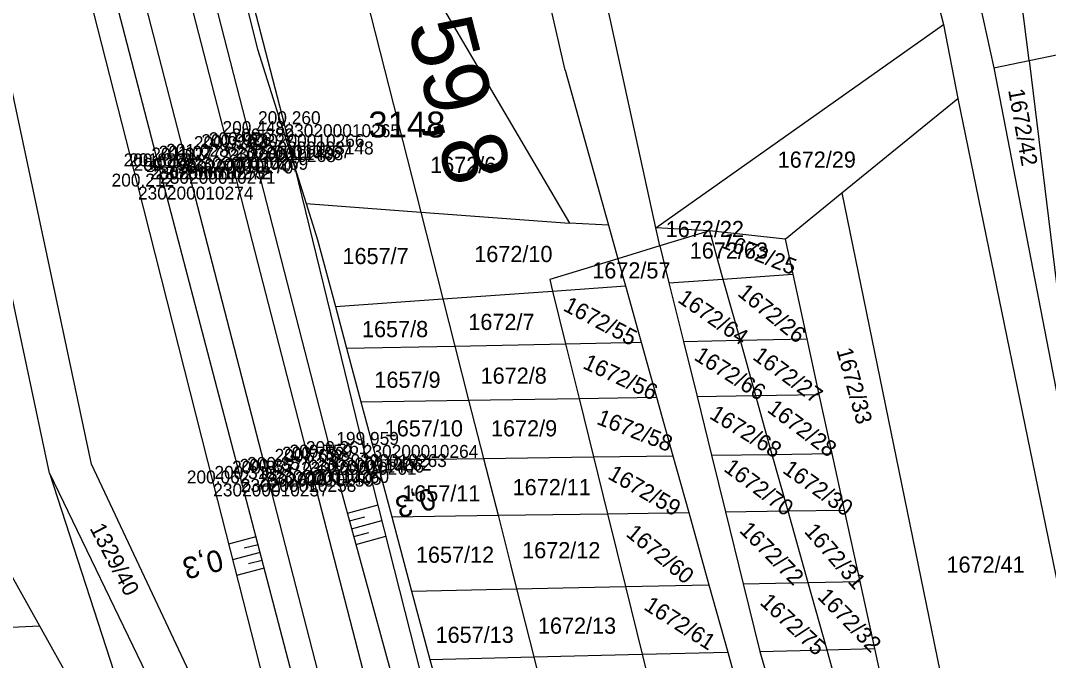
# Model space of a CAD drawing. Extents: x -563148 to -561712, y -1182311 to -1179502.
# Drawn here: x -562432.1 to -562336.8, y -1182001.5 to -1181942.2 of the extents above; entities that cross this region are included whole.
import ezdxf

# ---------------------------------------------------------------- set-up
doc = ezdxf.new("R2010")
doc.units = 0
for name, color, linetype in [('Vrstva 1', 7, 'Continuous'), ('Vrstva 4', 7, 'Continuous'), ('Vrstva 48', 7, 'Continuous'), ('Vrstva 49', 7, 'Continuous'), ('Vrstva 53', 7, 'Continuous'), ('Vrstva 55', 7, 'Continuous'), ('Vrstva 57', 7, 'Continuous'), ('Vrstva 60', 7, 'Continuous'), ('Vrstva 61', 7, 'Continuous'), ('Vrstva 63', 7, 'Continuous'), ('Vrstva 7', 7, 'Continuous')]:
    doc.layers.add(name, color=color, linetype=linetype)

msp = doc.modelspace()

# ---------------------------------------------------------------- linework, layer by layer
at = {"layer": 'Vrstva 1'}
for points in [[(-562431.456, -1181882.158), (-562425.093, -1181906.771), (-562419.091, -1181930.016), (-562412.913, -1181953.965), (-562405.427, -1181982.918), (-562399.924, -1182004.215), (-562394.072, -1182026.888), (-562387.874, -1182050.84), (-562381.86, -1182074.092), (-562375.538, -1182098.521), (-562369.352, -1182122.433), (-562362.844, -1182147.635), (-562356.836, -1182170.919), (-562350.524, -1182195.336)], [(-562435.353, -1181883.455), (-562429.043, -1181907.884), (-562423.025, -1181931.202), (-562416.86, -1181955.033), (-562409.363, -1181984.042), (-562403.855, -1182005.364), (-562398.009, -1182028.011), (-562391.856, -1182051.875), (-562385.852, -1182075.188), (-562379.546, -1182099.541), (-562373.358, -1182123.485), (-562366.843, -1182148.681), (-562360.825, -1182171.976), (-562354.524, -1182196.409)]]:
    msp.add_lwpolyline(points, dxfattribs=at)
at = {"layer": 'Vrstva 4'}
for points in [[(-562356.597, -1182197.058), (-562363.671, -1182172.63), (-562369.111, -1182150.394), (-562376.003, -1182124.384), (-562381.959, -1182100.171), (-562388.242, -1182075.655), (-562394.258, -1182052.529), (-562401.091, -1182025.773), (-562406.12, -1182006.052), (-562411.703, -1181984.696), (-562419.188, -1181956.156), (-562425.491, -1181931.882), (-562431.354, -1181908.293), (-562438.222, -1181883.645), (-562444.124, -1181860.119), (-562450.397, -1181835.425), (-562455.984, -1181813.76), (-562461.844, -1181791.501), (-562470.013, -1181759.746), (-562475.447, -1181735.97), (-562481.267, -1181709.546), (-562485.292, -1181688.623), (-562489.631, -1181662.779), (-562492.854, -1181639.283)], [(-562429.083, -1181881.427), (-562423.039, -1181906.026), (-562416.991, -1181929.289), (-562410.946, -1181952.751), (-562403.313, -1181982.397), (-562397.583, -1182003.414), (-562392.555, -1182023.727), (-562385.634, -1182050.403), (-562379.578, -1182073.569), (-562373.303, -1182097.775), (-562367.317, -1182121.855), (-562360.795, -1182147.202), (-562354.718, -1182170.426), (-562348.388, -1182194.775)]]:
    msp.add_lwpolyline(points, dxfattribs=at)
at = {"layer": 'Vrstva 48'}
for p, q in [((-562401.821, -1181987.868), (-562398.985, -1181987.095)), ((-562401.624, -1181988.592), (-562400.212, -1181988.207)), ((-562401.427, -1181989.315), (-562398.615, -1181988.549)), ((-562410.299, -1181990.068), (-562412.834, -1181990.731)), ((-562401.23, -1181990.039), (-562399.83, -1181989.657)), ((-562401.032, -1181990.763), (-562398.246, -1181990.003)), ((-562410.109, -1181990.794), (-562411.379, -1181991.126)), ((-562409.919, -1181991.519), (-562412.464, -1181992.185)), ((-562409.729, -1181992.245), (-562411.004, -1181992.578)), ((-562409.54, -1181992.971), (-562412.094, -1181993.638))]:
    msp.add_line(p, q, dxfattribs=at)
at = {"layer": 'Vrstva 49'}
for points in [[(-562356.597, -1182197.058), (-562363.671, -1182172.63), (-562369.111, -1182150.394), (-562376.003, -1182124.384), (-562381.959, -1182100.171), (-562388.242, -1182075.655), (-562394.258, -1182052.529), (-562401.091, -1182025.773), (-562406.12, -1182006.052), (-562411.703, -1181984.696), (-562419.188, -1181956.156), (-562425.491, -1181931.882), (-562431.354, -1181908.293), (-562438.222, -1181883.645), (-562444.124, -1181860.119), (-562450.397, -1181835.425), (-562455.984, -1181813.76), (-562461.844, -1181791.501), (-562470.013, -1181759.746), (-562475.447, -1181735.97), (-562481.267, -1181709.546), (-562485.292, -1181688.623), (-562489.631, -1181662.779), (-562492.854, -1181639.283)], [(-562348.388, -1182194.775), (-562346.233, -1182193.909), (-562352.64, -1182170.226), (-562359.021, -1182146.828), (-562365.116, -1182121.8), (-562371.268, -1182096.806), (-562377.938, -1182072.997), (-562383.189, -1182049.641), (-562389.659, -1182023.356), (-562394.989, -1182002.824), (-562400.393, -1181981.55), (-562407.655, -1181951.839), (-562413.753, -1181928.351), (-562419.93, -1181905.004), (-562426.042, -1181880.285)], [(-562429.083, -1181881.427), (-562423.039, -1181906.026), (-562416.991, -1181929.289), (-562410.946, -1181952.751), (-562403.313, -1181982.397), (-562397.583, -1182003.414), (-562392.555, -1182023.727), (-562385.634, -1182050.403), (-562379.578, -1182073.569), (-562373.303, -1182097.775), (-562367.317, -1182121.855), (-562360.795, -1182147.202), (-562354.718, -1182170.426), (-562348.388, -1182194.775)], [(-562439.741, -1181884.96), (-562433.646, -1181909.277), (-562427.61, -1181932.656), (-562421.237, -1181957.617), (-562414.263, -1181985.119), (-562408.778, -1182006.666), (-562403.486, -1182026.149), (-562396.951, -1182053.474), (-562390.332, -1182076.348), (-562384.199, -1182100.797), (-562378.1, -1182124.825), (-562372.04, -1182148.774), (-562365.699, -1182172.919), (-562358.847, -1182197.091), (-562356.597, -1182197.058)]]:
    msp.add_lwpolyline(points, dxfattribs=at)
at = {"layer": 'Vrstva 53'}
for p, q in [((-562420.91, -1181902.74), (-562410.15, -1181944.88)), ((-562410.15, -1181944.88), (-562405.65, -1181959.2)), ((-562425.54, -1181983.33), (-562432.92, -1181948.58)), ((-562405.65, -1181959.2), (-562404.6, -1181962.54)), ((-562404.6, -1181962.54), (-562402.94, -1181968.72)), ((-562402.94, -1181968.72), (-562401.9, -1181972.6)), ((-562401.9, -1181972.6), (-562400.57, -1181977.57)), ((-562400.57, -1181977.57), (-562399.13, -1181982.94)), ((-562399.13, -1181982.94), (-562397.71, -1181988.21)), ((-562403.38, -1182030.44), (-562425.54, -1181983.33)), ((-562397.71, -1181988.21), (-562395.87, -1181995.1)), ((-562395.87, -1181995.1), (-562394.17, -1182001.42)), ((-562394.17, -1182001.42), (-562391.09, -1182012.89))]:
    msp.add_line(p, q, dxfattribs=at)
at = {"layer": 'Vrstva 55'}
for p, q in [((-562372.35, -1181842.15), (-562346.55, -1181942.6)), ((-562338.63, -1181945.94), (-562346.12, -1181884.73)), ((-562373.23, -1181961.44), (-562383.8, -1181913.17)), ((-562381.62, -1181946.84), (-562388.61, -1181916.83)), ((-562405.15, -1181920.27), (-562395.02, -1181959.99)), ((-562405.15, -1181920.27), (-562381.24, -1181961.01)), ((-562343.26, -1181940.43), (-562341.89, -1181946.62)), ((-562373.23, -1181961.44), (-562346.55, -1181942.6)), ((-562346.55, -1181942.6), (-562345.24, -1181949.46)), ((-562338.63, -1181945.94), (-562334.86, -1181945.16)), ((-562341.89, -1181946.62), (-562338.63, -1181945.94)), ((-562341.89, -1181946.62), (-562332.75, -1181993.96)), ((-562338.63, -1181945.94), (-562332.75, -1181993.96)), ((-562381.62, -1181946.84), (-562377.62, -1181961.2)), ((-562355.97, -1181958.2), (-562345.24, -1181949.46)), ((-562345.24, -1181949.46), (-562335.42, -1181997.15)), ((-562361.25, -1181962.5), (-562355.97, -1181958.2)), ((-562355.97, -1181958.2), (-562338.86, -1182041.71)), ((-562405.65, -1181959.2), (-562395.02, -1181959.99)), ((-562395.02, -1181959.99), (-562392.97, -1181968.02)), ((-562395.02, -1181959.99), (-562381.24, -1181961.01)), ((-562377.62, -1181961.2), (-562381.24, -1181961.01)), ((-562377.62, -1181961.2), (-562376.75, -1181964.31)), ((-562372.86, -1181963.12), (-562373.23, -1181961.44)), ((-562368.26, -1181961.71), (-562373.23, -1181961.44)), ((-562368.26, -1181961.71), (-562372.86, -1181963.12)), ((-562361.25, -1181962.5), (-562368.26, -1181961.71)), ((-562368.26, -1181961.71), (-562367.01, -1181966.18)), ((-562361.25, -1181962.5), (-562360.54, -1181965.73)), ((-562372.86, -1181963.12), (-562376.75, -1181964.31)), ((-562372.86, -1181963.12), (-562372.02, -1181966.54)), ((-562429.45, -1181984.16), (-562433.59, -1181964.66)), ((-562376.75, -1181964.31), (-562383.06, -1181966.24)), ((-562376.75, -1181964.31), (-562376.05, -1181966.82)), ((-562367.01, -1181966.18), (-562360.54, -1181965.73)), ((-562360.54, -1181965.73), (-562359.23, -1181971.72)), ((-562383.06, -1181966.24), (-562382.8, -1181967.3)), ((-562372.02, -1181966.54), (-562367.01, -1181966.18)), ((-562372.02, -1181966.54), (-562370.67, -1181971.96)), ((-562367.01, -1181966.18), (-562365.42, -1181971.85)), ((-562392.97, -1181968.02), (-562382.8, -1181967.3)), ((-562382.8, -1181967.3), (-562376.05, -1181966.82)), ((-562382.8, -1181967.3), (-562381.59, -1181972.18)), ((-562376.05, -1181966.82), (-562374.59, -1181972.04)), ((-562402.94, -1181968.72), (-562392.97, -1181968.02)), ((-562392.97, -1181968.02), (-562391.86, -1181972.39)), ((-562401.9, -1181972.6), (-562391.86, -1181972.39)), ((-562391.86, -1181972.39), (-562381.59, -1181972.18)), ((-562391.86, -1181972.39), (-562390.58, -1181977.41)), ((-562381.59, -1181972.18), (-562374.59, -1181972.04)), ((-562381.59, -1181972.18), (-562380.34, -1181977.24)), ((-562374.59, -1181972.04), (-562373.16, -1181977.12)), ((-562370.67, -1181971.96), (-562365.42, -1181971.85)), ((-562370.67, -1181971.96), (-562369.41, -1181977.06)), ((-562365.42, -1181971.85), (-562359.23, -1181971.72)), ((-562365.42, -1181971.85), (-562363.98, -1181976.97)), ((-562359.23, -1181971.72), (-562358.11, -1181976.87)), ((-562380.34, -1181977.24), (-562373.16, -1181977.12)), ((-562373.16, -1181977.12), (-562371.64, -1181982.56)), ((-562369.41, -1181977.06), (-562363.98, -1181976.97)), ((-562369.41, -1181977.06), (-562368.06, -1181982.51)), ((-562363.98, -1181976.97), (-562358.11, -1181976.87)), ((-562363.98, -1181976.97), (-562362.46, -1181982.43)), ((-562358.11, -1181976.87), (-562356.91, -1181982.35)), ((-562400.57, -1181977.57), (-562390.58, -1181977.41)), ((-562390.58, -1181977.41), (-562380.34, -1181977.24)), ((-562390.58, -1181977.41), (-562389.2, -1181982.8)), ((-562380.34, -1181977.24), (-562379, -1181982.66)), ((-562399.13, -1181982.94), (-562389.2, -1181982.8)), ((-562389.2, -1181982.8), (-562379, -1181982.66)), ((-562389.2, -1181982.8), (-562387.86, -1181988.07)), ((-562379, -1181982.66), (-562371.64, -1181982.56)), ((-562379, -1181982.66), (-562377.7, -1181987.92)), ((-562371.64, -1181982.56), (-562370.18, -1181987.8)), ((-562368.06, -1181982.51), (-562362.46, -1181982.43)), ((-562368.06, -1181982.51), (-562366.77, -1181987.75)), ((-562362.46, -1181982.43), (-562356.91, -1181982.35)), ((-562362.46, -1181982.43), (-562360.99, -1181987.66)), ((-562356.91, -1181982.35), (-562355.76, -1181987.59)), ((-562429.45, -1181984.16), (-562399.59, -1182045.91)), ((-562429.45, -1181984.16), (-562417.31, -1182021.52)), ((-562366.77, -1181987.75), (-562360.99, -1181987.66)), ((-562360.99, -1181987.66), (-562355.76, -1181987.59)), ((-562360.99, -1181987.66), (-562359.13, -1181994.3)), ((-562355.76, -1181987.59), (-562354.32, -1181994.2)), ((-562397.71, -1181988.21), (-562387.86, -1181988.07)), ((-562387.86, -1181988.07), (-562377.7, -1181987.92)), ((-562387.86, -1181988.07), (-562386.7, -1181992.62)), ((-562377.7, -1181987.92), (-562370.18, -1181987.8)), ((-562377.7, -1181987.92), (-562376.03, -1181994.67)), ((-562370.18, -1181987.8), (-562368.3, -1181994.5)), ((-562366.77, -1181987.75), (-562365.12, -1181994.43)), ((-562434.15, -1181991.61), (-562430.38, -1181998.32)), ((-562386.7, -1181992.62), (-562386.13, -1181994.89)), ((-562365.12, -1181994.43), (-562359.13, -1181994.3)), ((-562359.13, -1181994.3), (-562354.32, -1181994.2)), ((-562359.13, -1181994.3), (-562357.38, -1182000.53)), ((-562354.32, -1181994.2), (-562352.96, -1182000.42)), ((-562395.87, -1181995.1), (-562386.13, -1181994.89)), ((-562386.13, -1181994.89), (-562376.03, -1181994.67)), ((-562386.13, -1181994.89), (-562384.55, -1182001.18)), ((-562376.03, -1181994.67), (-562368.3, -1181994.5)), ((-562376.03, -1181994.67), (-562374.48, -1182000.94)), ((-562368.3, -1181994.5), (-562366.55, -1182000.75)), ((-562365.12, -1181994.43), (-562363.57, -1182000.68)), ((-562465.25, -1181999.74), (-562430.38, -1181998.32)), ((-562430.38, -1181998.32), (-562426.64, -1182004.97)), ((-562384.55, -1182001.18), (-562374.48, -1182000.94)), ((-562374.48, -1182000.94), (-562366.55, -1182000.75)), ((-562374.48, -1182000.94), (-562371.61, -1182012.56)), ((-562366.55, -1182000.75), (-562363.29, -1182012.41)), ((-562363.57, -1182000.68), (-562357.38, -1182000.53)), ((-562363.57, -1182000.68), (-562360.19, -1182012.36)), ((-562357.38, -1182000.53), (-562352.96, -1182000.42)), ((-562357.38, -1182000.53), (-562354.1, -1182012.25)), ((-562352.96, -1182000.42), (-562350.38, -1182012.19)), ((-562394.17, -1182001.42), (-562384.55, -1182001.18)), ((-562384.55, -1182001.18), (-562381.64, -1182012.73))]:
    msp.add_line(p, q, dxfattribs=at)
at = {"layer": 'Vrstva 60'}
for p, q in [((-562407.655, -1181951.839), (-562407.655, -1181951.839)), ((-562410.946, -1181952.751), (-562410.946, -1181952.751)), ((-562413.606, -1181954.143), (-562413.606, -1181954.143)), ((-562412.913, -1181953.965), (-562412.913, -1181953.965)), ((-562412.22, -1181953.788), (-562412.22, -1181953.788)), ((-562410.099, -1181953.438), (-562410.099, -1181953.438)), ((-562417.551, -1181955.205), (-562417.551, -1181955.205)), ((-562416.86, -1181955.033), (-562416.86, -1181955.033)), ((-562416.168, -1181954.86), (-562416.168, -1181954.86)), ((-562420.12, -1181955.751), (-562420.12, -1181955.751)), ((-562419.632, -1181955.734), (-562419.632, -1181955.734)), ((-562419.188, -1181956.156), (-562419.188, -1181956.156)), ((-562421.237, -1181957.617), (-562421.237, -1181957.617)), ((-562400.393, -1181981.55), (-562400.393, -1181981.55)), ((-562405.427, -1181982.918), (-562405.427, -1181982.918)), ((-562404.736, -1181982.724), (-562404.736, -1181982.724)), ((-562403.313, -1181982.397), (-562403.313, -1181982.397)), ((-562408.667, -1181983.868), (-562408.667, -1181983.868)), ((-562406.119, -1181983.112), (-562406.119, -1181983.112)), ((-562411.703, -1181984.696), (-562411.703, -1181984.696)), ((-562410.059, -1181984.215), (-562410.059, -1181984.215)), ((-562409.363, -1181984.042), (-562409.363, -1181984.042)), ((-562414.263, -1181985.119), (-562414.263, -1181985.119))]:
    msp.add_line(p, q, dxfattribs=at)
at = {"layer": 'Vrstva 63'}
msp.add_line((-562410.149, -1181953.438), (-562410.049, -1181953.438), dxfattribs=at)
msp.add_circle((-562410.099, -1181953.438), 0.756, dxfattribs=at)
at = {"layer": 'Vrstva 7'}
for p, q in [((-562419.632, -1181955.234), (-562419.632, -1181956.234)), ((-562420.133, -1181955.703), (-562420.107, -1181955.799)), ((-562420.132, -1181955.734), (-562419.132, -1181955.734))]:
    msp.add_line(p, q, dxfattribs=at)
for centre, radius in [((-562416.89, -1181954.916), 0.75), ((-562420.12, -1181955.751), 0.5)]:
    msp.add_circle(centre, radius, dxfattribs=at)

# ---------------------------------------------------------------- texts
at = {"layer": 'Vrstva 48'}
for rotation, p in [(195.25027, (-562393.961, -1181985.473)), (194.28187, (-562413.653, -1181991.181))]:
    msp.add_text('0,3', height=2, rotation=rotation, dxfattribs=at).set_placement(p)
at = {"layer": 'Vrstva 57'}
for s, rotation, p in [('1672/42', 280.23687, (-562340.57, -1181948.68)), ('1672/25', 338.82741, (-562367.32, -1181963.21)), ('1672/64', 325.27656, (-562371.3, -1181968.25)), ('1672/26', 320.95143, (-562365.74, -1181967.65)), ('1672/55', 332.27325, (-562381.91, -1181969.05)), ('1672/56', 335.13633, (-562380.09, -1181974.41)), ('1672/66', 327.51036, (-562369.78, -1181973.6)), ('1672/27', 323.93061, (-562364.34, -1181973.55)), ('1672/33', 285.43968, (-562356.5, -1181972.76)), ('1672/68', 328.30281, (-562368.35, -1181979.03)), ('1672/28', 323.172, (-562363, -1181978.42)), ('1672/58', 338.69556, (-562378.81, -1181979.58)), ('1672/59', 330.22386, (-562377.78, -1181984.62)), ('1672/70', 323.36586, (-562367.02, -1181983.9)), ('1672/30', 324.80415, (-562361.57, -1181984.06)), ('1329/40', 297.75852, (-562425.75, -1181989.27)), ('1672/60', 320.47515, (-562376.08, -1181989.92)), ('1672/72', 315, (-562365.56, -1181989.55)), ('1672/31', 311.21838, (-562359.54, -1181989.61)), ('1672/32', 314.20431, (-562358.32, -1181995.7)), ('1672/61', 327.41307, (-562374.43, -1181996.73)), ('1672/75', 317.17476, (-562363.67, -1181996.24))]:
    msp.add_text(s, height=1.5, rotation=rotation, dxfattribs=at).set_placement(p)
for s, p in [('1672/29', (-562361.93, -1181955.87)), ('1672/6', (-562394.15, -1181956.36)), ('1672/22', (-562372.31, -1181962.3)), ('1672/63', (-562370.08, -1181964.29)), ('1657/7', (-562402.28, -1181964.8)), ('1672/10', (-562390.06, -1181964.61)), ('1672/57', (-562379.12, -1181966.13)), ('1672/7', (-562390.61, -1181970.9)), ('1657/8', (-562400.47, -1181971.57)), ('1672/8', (-562389.47, -1181975.88)), ('1657/9', (-562399.32, -1181976.26)), ('1657/10', (-562398.36, -1181980.76)), ('1672/9', (-562388.51, -1181980.76)), ('1672/11', (-562386.5, -1181986.21)), ('1657/11', (-562396.74, -1181986.79)), ('1672/12', (-562385.62, -1181992.05)), ('1657/12', (-562395.47, -1181992.47)), ('1672/41', (-562346.28, -1181993.38)), ('1672/13', (-562384.16, -1181999.04)), ('1657/13', (-562393.65, -1181999.89))]:
    msp.add_text(s, height=1.5, dxfattribs=at).set_placement(p)
at = {"layer": 'Vrstva 60'}
for s, p in [('230200010265', (-562407.655, -1181953.039)), ('230200010266', (-562410.946, -1181953.951)), ('230200010268', (-562413.606, -1181955.343)), ('230200011408', (-562412.913, -1181955.165)), ('230200010267', (-562412.22, -1181954.988)), ('230200003148', (-562410.099, -1181954.638)), ('230200010270', (-562417.551, -1181956.405)), ('230200011407', (-562416.86, -1181956.233)), ('230200010269', (-562416.168, -1181956.06)), ('230200010273', (-562420.12, -1181956.951)), ('230200010272', (-562419.632, -1181956.934)), ('230200010271', (-562419.188, -1181957.356)), ('230200010274', (-562421.237, -1181958.817)), ('230200010264', (-562400.393, -1181982.75)), ('230200011406', (-562405.427, -1181984.118)), ('230200010262', (-562404.736, -1181983.924)), ('230200010263', (-562403.313, -1181983.597)), ('230200010260', (-562408.667, -1181985.068)), ('230200010261', (-562406.119, -1181984.312)), ('230200010258', (-562411.703, -1181985.896)), ('230200010259', (-562410.059, -1181985.415)), ('230200011405', (-562409.363, -1181985.242)), ('230200010257', (-562414.263, -1181986.319))]:
    msp.add_text(s, height=1.2, dxfattribs=at).set_placement(p)
at = {"layer": 'Vrstva 61'}
for s, p in [('200.260', (-562410.106, -1181951.839)), ('200.448', (-562413.4, -1181952.751)), ('200.389', (-562412.553, -1181953.438)), ('200.920', (-562416.057, -1181954.143)), ('200.920', (-562415.364, -1181953.965)), ('200.926', (-562414.672, -1181953.788)), ('201.027', (-562420.003, -1181955.205)), ('201.027', (-562419.312, -1181955.033)), ('201.028', (-562418.622, -1181954.86)), ('200.887', (-562422.572, -1181955.751)), ('201.012', (-562422.08, -1181955.734)), ('200.496', (-562421.64, -1181956.156)), ('200.212', (-562423.685, -1181957.617)), ('199.959', (-562402.847, -1181981.55)), ('200.763', (-562408.571, -1181983.112)), ('200.759', (-562407.881, -1181982.918)), ('200.759', (-562407.19, -1181982.724)), ('200.261', (-562405.67, -1181982.397)), ('200.857', (-562411.815, -1181984.042)), ('200.857', (-562411.119, -1181983.868)), ('200.312', (-562414.151, -1181984.696)), ('200.857', (-562412.511, -1181984.215)), ('200.062', (-562416.711, -1181985.119))]:
    msp.add_text(s, height=1.2, dxfattribs=at).set_placement(p)
at = {"layer": 'Vrstva 63'}
msp.add_text('3148', height=2.4, dxfattribs=at).set_placement((-562399.878, -1181953.067))
at = {"layer": 'Vrstva 7'}
msp.add_text('59,8', height=6, rotation=284.4903, dxfattribs=at).set_placement((-562396.273, -1181942.748))

doc.saveas('drawing.dxf')
